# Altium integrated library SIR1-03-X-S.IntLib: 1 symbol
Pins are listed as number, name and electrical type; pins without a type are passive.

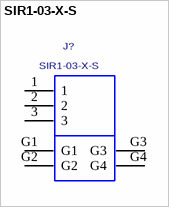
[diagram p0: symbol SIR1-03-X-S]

## SIR1-03-X-S
designator J?
ONE PIECE POWER RIGHT ANGLE ASSEMBLY.; MANUFACTURER: SAMTEC
footprint SIR1-03-X-S
pins: 1, 2, 3, G1, G2, G3, G4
